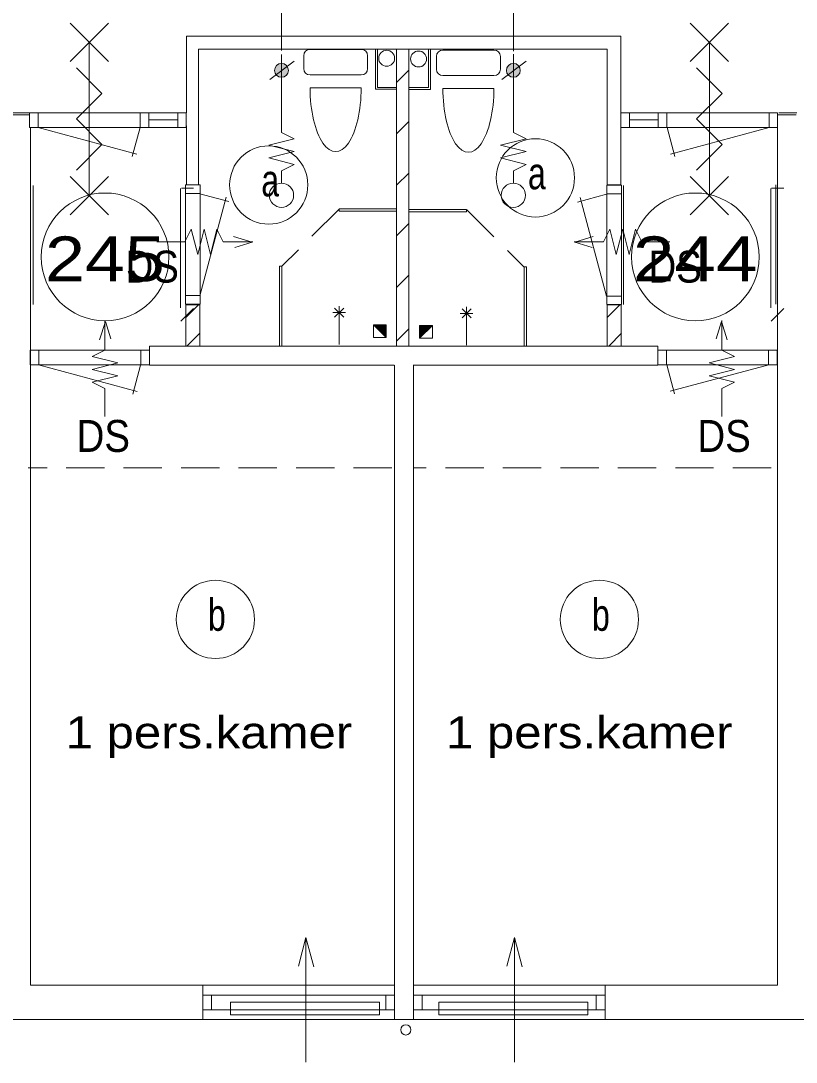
# Model space of a CAD drawing. Extents: x 295824 to 414724, y 24924 to 109024.
# Drawn here: x 314015 to 320086, y 87221 to 95369 of the extents above; entities that cross this region are included whole.
import ezdxf
from ezdxf.enums import TextEntityAlignment as Align

# ---------------------------------------------------------------- set-up
doc = ezdxf.new("R2010")
doc.units = 0
doc.header["$LTSCALE"] = 100
doc.linetypes.add('MEDIUM_DASHED', pattern=[4.5, 3, -1.5])
for name, color, linetype, lineweight in [('1', 7, 'Continuous', 13), ('16', 7, 'Continuous', 13), ('24', 7, 'Continuous', 13), ('61', 7, 'Continuous', 13)]:
    doc.layers.add(name, color=color, linetype=linetype, lineweight=lineweight)

msp = doc.modelspace()

# ---------------------------------------------------------------- hatches: boundary and pattern name
at = {"layer": '24'}
for points in [[(316110.5, 94981.2, 1), (316001.9, 94981.2, 1)], [(317926, 94981.2, 1), (317817.4, 94981.2, 1)]]:
    msp.add_hatch(color=256, dxfattribs=at).paths.add_polyline_path(points)
at = {"layer": '61'}
for points in [[(316775.3, 92991.3), (316875.3, 92891.3), (316875.3, 92991.3)], [(317237.7, 92985.9), (317137.7, 92885.9), (317137.7, 92985.9)]]:
    msp.add_hatch(color=256, dxfattribs=at).paths.add_polyline_path(points)

# ---------------------------------------------------------------- linework, layer by layer
at = {"layer": '1'}
for p, q in [((316056.2, 95135.8), (316056.2, 96018.7)), ((317871.7, 95130.8), (317871.7, 96018.7))]:
    msp.add_line(p, q, dxfattribs=at)
at = {"layer": '16'}
for p, q in [((315450.2, 93739.9), (315400.2, 93539.9)), ((318727.6, 93739.9), (318777.6, 93539.9)), ((314573.7, 92641.7), (314773.7, 92591.7)), ((319604, 92641.7), (319404, 92591.7))]:
    msp.add_line(p, q, dxfattribs=at)
at = {"layer": '24'}
for p, q in [((316056.2, 94545.8), (316056.2, 95106.6)), ((317871.7, 94545.8), (317871.7, 95108.1)), ((315964.6, 94910.4), (316156.1, 95052.1)), ((317780.1, 94910.4), (317971.7, 95052.1)), ((315825.6, 93636.5), (315681.4, 93681.5)), ((315689.8, 93594.1), (315825.6, 93636.5)), ((318352.2, 93636.5), (318496.4, 93681.5)), ((318488, 93594.1), (318352.2, 93636.5)), ((314677.1, 93017.1), (314632.1, 92872.9)), ((314719.5, 92881.3), (314677.1, 93017.1)), ((319458.2, 92881.3), (319500.7, 93017.1)), ((319500.7, 93017.1), (319545.7, 92872.9)), ((316247.7, 88195.7), (316188.1, 87973.2)), ((317880, 88195.7), (317820.5, 87973.2))]:
    msp.add_line(p, q, dxfattribs=at)
for points in [[(316056.2, 94095.8), (316056.2, 94195.8), (316156.2, 94245.8), (315956.2, 94295.8), (316156.2, 94345.8), (315956.2, 94395.8), (316156.2, 94445.8), (316056.2, 94495.8), (316056.2, 94545.8)], [(317871.7, 94095.8), (317871.7, 94195.8), (317971.7, 94245.8), (317771.7, 94295.8), (317971.7, 94345.8), (317771.7, 94395.8), (317971.7, 94445.8), (317871.7, 94495.8), (317871.7, 94545.8)], [(315400.2, 93539.9), (315350.2, 93739.9), (315300.2, 93639.9), (315081.4, 93639.9)], [(315831.4, 93639.9), (315600.2, 93639.9), (315550.2, 93739.9), (315500.2, 93539.9), (315450.2, 93739.9)], [(318346.4, 93639.9), (318577.6, 93639.9), (318627.6, 93739.9), (318677.6, 93539.9), (318727.6, 93739.9)], [(318777.6, 93539.9), (318827.6, 93739.9), (318877.6, 93639.9), (319096.4, 93639.9)], [(314673.7, 93023), (314673.7, 92791.7), (314573.7, 92741.7), (314773.7, 92691.7), (314573.7, 92641.7)], [(319504, 93023), (319504, 92791.7), (319604, 92741.7), (319404, 92691.7), (319604, 92641.7)], [(314773.7, 92591.7), (314573.7, 92541.7), (314673.7, 92491.7), (314673.7, 92273)], [(319404, 92591.7), (319604, 92541.7), (319504, 92491.7), (319504, 92273)], [(316247.7, 87220.7), (316247.7, 88195.7), (316309.4, 87965.5)], [(317880, 87220.7), (317880, 88195.7), (317941.7, 87965.5)]]:
    msp.add_lwpolyline(points, dxfattribs=at)
for points in [[(315656.4, 87691.5), (316822.4, 87691.5), (316822.4, 87591.5), (315656.4, 87591.5)], [(317288.7, 87691.5), (318454.7, 87691.5), (318454.7, 87591.5), (317288.7, 87591.5)]]:
    msp.add_lwpolyline(points, close=True, dxfattribs=at)
for centre, radius in [((316056.2, 94981.2), 54.3), ((317871.7, 94981.2), 54.3), ((316056.2, 94004.2), 95), ((317871.7, 94004.2), 95)]:
    msp.add_circle(centre, radius, dxfattribs=at)
at = {"layer": '61'}
for p, q in [((314400.4, 95051.1), (314700.4, 95351.1)), ((314700.4, 95051.1), (314400.4, 95351.1)), ((319256.2, 95051.1), (319556.2, 95351.1)), ((319556.2, 95051.1), (319256.2, 95351.1)), ((314550.4, 95201.1), (314550.4, 94001.1)), ((319406.2, 95201.1), (319406.2, 94001.1)), ((315407, 94086.3), (315407, 95148.4)), ((316230.2, 94995.4), (316230.2, 95095.4)), ((316280.2, 95145.4), (316680.2, 95145.4)), ((316730.2, 95095.4), (316730.2, 94995.4)), ((316807, 94848.4), (316807, 95148.4)), ((316957, 92823.4), (316957, 95148.4)), ((317053.3, 92823.4), (317053.3, 95148.4)), ((317207.1, 95147.9), (317207.1, 94847.9)), ((317319.6, 95140.5), (317719.6, 95140.5)), ((317269.6, 94990.5), (317269.6, 95090.5)), ((317769.6, 95090.5), (317769.6, 94990.5)), ((316680.2, 94945.4), (316280.2, 94945.4)), ((317052.8, 94982.4), (316957, 94886.7)), ((317719.6, 94940.5), (317319.6, 94940.5)), ((316957, 94848.4), (316807, 94848.4)), ((317207.1, 94847.9), (317057.1, 94847.9)), ((316280.2, 94845.4), (316680.2, 94845.4)), ((317319.6, 94840.5), (317719.6, 94840.5)), ((313944.8, 94648.3), (314086, 94648.3)), ((313944.8, 94633.3), (314086, 94633.3)), ((314150.8, 94648.3), (314150.8, 94534.3)), ((314950.8, 94648.3), (314950.8, 94534.3)), ((315017.8, 94648.3), (315017.8, 94534.3)), ((315243.8, 94648.3), (315243.8, 94534.3)), ((318712.3, 94084.9), (318712.3, 94650.7)), ((318780.5, 94648.3), (318780.5, 94534.3)), ((319006.5, 94648.3), (319006.5, 94534.3)), ((319073.5, 94648.3), (319073.5, 94534.3)), ((319873.5, 94648.3), (319873.5, 94534.3)), ((319944.4, 94633.3), (320085.5, 94633.3)), ((319949.3, 94648.3), (320090.5, 94648.3)), ((314090.1, 94533.5), (314090.1, 87823.4)), ((314150.1, 94533.7), (314922.8, 94326.6)), ((314948.5, 94533.1), (314887.7, 94306.2)), ((315243.8, 94594.2), (315017.8, 94594.2)), ((315312.3, 94086.3), (315312.3, 94548.4)), ((317052.8, 94581.5), (316957, 94485.8)), ((318780.5, 94594.2), (319006.5, 94594.2)), ((319075.8, 94533.1), (319136.6, 94306.2)), ((319874.2, 94533.7), (319101.5, 94326.6)), ((319940.1, 94548.4), (319940.1, 87823.4)), ((314400.4, 93851.1), (314700.4, 94151.1)), ((314700.4, 93851.1), (314400.4, 94151.1)), ((317052.8, 94178.2), (316957, 94082.4)), ((319256.2, 93851.1), (319556.2, 94151.1)), ((319556.2, 93851.1), (319256.2, 94151.1)), ((314112.5, 93148.9), (314112.5, 94081.3)), ((315264.9, 93123.7), (315264.9, 94057.7)), ((315367.2, 94058.5), (315272.4, 94058.5)), ((315304.8, 93151.5), (315304.8, 94085.5)), ((315407, 94086.3), (315312.3, 94086.3)), ((318712.3, 94084.9), (318607, 94084.9)), ((318718.2, 93148.9), (318718.2, 94081.3)), ((318734.1, 93148.9), (318734.1, 94081.3)), ((319886.5, 93123.7), (319886.5, 94057.7)), ((319988.8, 94058.5), (319894, 94058.5)), ((319926.4, 93151.5), (319926.4, 94085.5)), ((315304.8, 94018.5), (315418.8, 94018.5)), ((315416.8, 93217.8), (315623.9, 93990.5)), ((315417.5, 94016.2), (315644.3, 93955.4)), ((318600.4, 94011.9), (318373.6, 93951.2)), ((318601.1, 93213.5), (318394, 93986.3)), ((318718.2, 94014.3), (318604.2, 94014.3)), ((316958.2, 93897), (316508.7, 93897)), ((316508.7, 93897), (316508.7, 93879)), ((316957.8, 93879), (316508.7, 93879)), ((317054.8, 93891.6), (317504.3, 93891.6)), ((317055.2, 93873.6), (317504.3, 93873.6)), ((317504.3, 93891.6), (317504.3, 93873.6)), ((317052.8, 93782.2), (316957, 93686.4)), ((316057.8, 92829), (316057.8, 93449.5)), ((317955.2, 92823.6), (317955.2, 93444.1)), ((317052.8, 93377.6), (316957, 93281.8)), ((315304.8, 93218.5), (315418.8, 93218.5)), ((315418.2, 93151.5), (315304.2, 93151.5)), ((315417.5, 93148), (315307.5, 93148)), ((315307.5, 93148), (315307.5, 92823.9)), ((315407.2, 93146.8), (315307.5, 93047.1)), ((315417.5, 93148), (315417.5, 92823.9)), ((318718.2, 93214.3), (318604.2, 93214.3)), ((318705.6, 93146.8), (318605.9, 93047.1)), ((318716.4, 93148), (318606.5, 93148)), ((318606.5, 93148), (318606.5, 92823.9)), ((318716.4, 93148), (318716.4, 92823.9)), ((315367.3, 93118.9), (315267.6, 93019.2)), ((316557.6, 93085.5), (316457.6, 93085.5)), ((316543, 93050.1), (316472.3, 93120.8)), ((316543, 93120.8), (316472.3, 93050.1)), ((316507.6, 93035.5), (316507.6, 93135.5)), ((317455.4, 93080.1), (317555.4, 93080.1)), ((317470, 93044.8), (317540.7, 93115.5)), ((317470, 93115.5), (317540.7, 93044.8)), ((317505.4, 93030.1), (317505.4, 93130.1)), ((319988.9, 93118.9), (319889.2, 93019.2)), ((316507.6, 93035.5), (316507.6, 92835.5)), ((317505.4, 93030.1), (317505.4, 92830.1)), ((315415.8, 92924.2), (315316.1, 92824.5)), ((317052.8, 92959.5), (316957, 92863.7)), ((318717.9, 92924.2), (318618.2, 92824.5)), ((315417.5, 92823.9), (315307.5, 92823.9)), ((318716.4, 92823.9), (318606.5, 92823.9)), ((314155.4, 92790.9), (314155.4, 92676.9)), ((314955.4, 92790.9), (314955.4, 92676.9)), ((315022.4, 92790.9), (315022.4, 92676.9)), ((319003.1, 92791.9), (319003.1, 92677.9)), ((319070.1, 92791.9), (319070.1, 92677.9)), ((319870.1, 92791.9), (319870.1, 92677.9)), ((314154.7, 92676.2), (314927.4, 92469.2)), ((314953.1, 92675.6), (314892.3, 92448.8)), ((316940.1, 87553.4), (316940.1, 92673.4)), ((317090.1, 87553.4), (317090.1, 92673.4)), ((319072.4, 92676.7), (319133.2, 92449.8)), ((319870.9, 92677.3), (319098.1, 92470.3)), ((314090.1, 87823.4), (316940.1, 87823.4)), ((315441, 87552.1), (315441, 87822.1)), ((319940.1, 87823.4), (317090.1, 87823.4)), ((318589.5, 87552.2), (318589.5, 87822.2)), ((315508.1, 87630.5), (315508.1, 87744.3)), ((316873.1, 87629.9), (316873.1, 87743.9)), ((317156.6, 87630.8), (317156.6, 87744.8)), ((318520.9, 87630.5), (318520.9, 87744.2)), ((326233, 87553.4), (307806, 87553.4))]:
    msp.add_line(p, q, dxfattribs=at)
at = {"layer": '61', "linetype": 'MEDIUM_DASHED'}
for p, q in [((316506.6, 93896.5), (316059.7, 93449.6)), ((317506.4, 93891.2), (317953.3, 93444.3)), ((316920.4, 91870), (314073.3, 91870)), ((319889.8, 91870), (317090.1, 91870))]:
    msp.add_line(p, q, dxfattribs=at)
at = {"layer": '61'}
for points in [[(318712.3, 94648.4), (318712.3, 95248.4), (315312.3, 95248.4), (315312.3, 94648.4)], [(318607, 94084.9), (318607, 95148.4), (315407, 95148.4)], [(316957, 94833.4), (316792, 94833.4), (316792, 95148.4)], [(317222.1, 95147.9), (317222.1, 94832.9), (317057.1, 94832.9)], [(314450.4, 95001.1), (314650.4, 94801.1), (314450.4, 94601.1), (314650.4, 94401.1), (314450.4, 94201.1)], [(319306.2, 95001.1), (319506.2, 94801.1), (319306.2, 94601.1), (319506.2, 94401.1), (319306.2, 94201.1)], [(316039.8, 92829), (316039.8, 93449.5), (316057.8, 93449.5)], [(317973.2, 92823.6), (317973.2, 93444.1), (317955.2, 93444.1)], [(316875.3, 92891.3), (316875.3, 92991.3), (316775.3, 92991.3)], [(317137.7, 92885.9), (317137.7, 92985.9), (317237.7, 92985.9)], [(317087.3, 92673.4), (319002.3, 92673.4), (319002.3, 92823.4), (315022.9, 92823.4)], [(316937.3, 92673.4), (315022.9, 92673.4), (315022.9, 92823.4)], [(314088.4, 92790.9), (314088.4, 92676.9), (315022.4, 92676.9)], [(315022.4, 92790.9), (314088.4, 92790.9), (314088.4, 92676.9)], [(319937.1, 92791.9), (319937.1, 92677.9), (319003.1, 92677.9)], [(319003.1, 92791.9), (319937.1, 92791.9), (319937.1, 92677.9)]]:
    msp.add_lwpolyline(points, dxfattribs=at)
for points in [[(315310.8, 94648.3), (315310.8, 94534.3), (314083.8, 94534.3), (314083.8, 94648.3)], [(315310.9, 94648.3), (315310.9, 94534.3), (314083.9, 94534.3), (314083.9, 94648.3)], [(319940.5, 94648.3), (319940.5, 94534.3), (318714.1, 94534.3), (318714.1, 94648.3)], [(319940.5, 94648.3), (319940.5, 94534.3), (318714.1, 94534.3), (318714.1, 94648.3)], [(315304.8, 93151.5), (315304.8, 94085.5), (315418.8, 94085.5), (315418.8, 93151.5)], [(318718.2, 94082.2), (318604.2, 94082.2), (318604.2, 93148.2), (318718.2, 93148.2)], [(316875.3, 92891.3), (316775.3, 92891.3), (316775.3, 92991.3)], [(316775.3, 92991.3), (316875.3, 92891.3), (316875.3, 92991.3)], [(317137.7, 92885.9), (317237.7, 92885.9), (317237.7, 92985.9)], [(317237.7, 92985.9), (317137.7, 92885.9), (317137.7, 92985.9)], [(315441.2, 87630.3), (315441.2, 87744.3), (316939.9, 87744.3), (316939.9, 87630.3)], [(317090.2, 87630.5), (317090.2, 87744.5), (318589.6, 87744.5), (318589.6, 87630.5)]]:
    msp.add_lwpolyline(points, close=True, dxfattribs=at)
for centre, radius in [((316879.5, 95075.9), 62.5), ((317129.5, 95070.4), 62.5), ((318044.2, 94140.2), 306.3), ((315956.1, 94084.5), 306.3), ((314675.2, 93521.8), 500), ((319296.8, 93521.8), 500), ((315538.5, 90685.4), 306.3), ((318545.3, 90685.4), 306.3), ((317029.6, 87473.2), 40)]:
    msp.add_circle(centre, radius, dxfattribs=at)
for centre, start, end in [((316280.2, 95095.4), 90, 180), ((316680.2, 95095.4), 0, 90), ((317319.6, 95090.5), 90, 180), ((317719.6, 95090.5), 0, 90), ((316280.2, 94995.4), 180, 270), ((316680.2, 94995.4), 270, 0), ((317319.6, 94990.5), 180, 270), ((317719.6, 94990.5), 270, 0)]:
    msp.add_arc(centre, 50, start, end, dxfattribs=at)
for centre in [(316480.2, 94845.4), (317519.6, 94840.5)]:
    msp.add_ellipse(centre, major_axis=(0, -500), ratio=0.4, start_param=4.712389, end_param=7.853982, dxfattribs=at)

# ---------------------------------------------------------------- texts
at = {"layer": '24', "width": 0.9}
for p in [(314835, 93320.9), (318929.4, 93320.9), (314451.9, 91995.9), (319312.5, 91995.9)]:
    msp.add_text('DS', height=250, dxfattribs=at).set_placement(p)
at = {"layer": '61'}
for s, width, p in [('a', 0.75, (317986.2, 94051)), ('a', 0.75, (315898.1, 93995.3)), ('b', 0.75, (315480.5, 90596.2)), ('b', 0.75, (318487.3, 90596.2)), ('1 pers.kamer', 1.15, (314366.1, 89676.2)), ('1 pers.kamer', 1.15, (317344.1, 89676.2))]:
    msp.add_text(s, height=250, dxfattribs=dict(at, width=width)).set_placement(p)
for s, width, p in [('245', 1.2, (314673.7, 93331.9)), ('244', 1.25, (319295.3, 93331.9))]:
    msp.add_text(s, height=350, dxfattribs=dict(at, width=width)).set_placement(p, align=Align.CENTER)

doc.saveas('drawing.dxf')
